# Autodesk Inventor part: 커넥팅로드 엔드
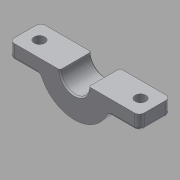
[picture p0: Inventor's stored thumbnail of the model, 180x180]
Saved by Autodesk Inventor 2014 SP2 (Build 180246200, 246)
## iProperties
Created: 2016-11
Part Number: 커넥팅로드 엔드
Material: 알루미늄 6061
Document SubType Name: Modeling
Designer: mduedu
Density: 2.71 g/cm^3
Mass: 15.0819 g
Surface Area: 26.6719 cm^2
Volume: 5.56529 cm^3
Appearance: 알루미늄 - 평지
Author: mduedu
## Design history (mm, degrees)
sketch "스케치1" dims "d0" = 30, "d3" = 15
  geometry: L1 (0, 0)-(0, 96); L2 (-5, 90.41)-(-10, 11.18); L3 (5, 90.41)-(10, 11.18); C1 r 6 at (0, 0); C2 r 4 at (0, 96); 3 further points
  constraints: 6 end point, 4 coincident, 2 centre point, 2 symmetric about line, 1 vertical, 6 other
  dimensions: "d1" = 12 diameter of C1; "d2" = 8 diameter of C2; "d4" = 96 distance of L1.start L1.end; "d6" = 10 distance from line of L1 L2.end; "d7" = 5 distance from line of L1 L2.start
extrude "돌출1" new body sketch "스케치1" stored distance "d8" = 13; taper "d9" = 0 deg
extrude "돌출2" join sketch "스케치1" stored distance "d10" = 32; taper "d11" = 0 deg
sketch "스케치2"
  geometry: L1 (5, 90.41)-(10, 11.18) reference; L2 (-5, 90.41)-(-10, 11.18) reference; A1 r 7.5 centre (0, 96) between (5, 90.41) and (-5, 90.41) reference; A2 r 15 centre (0, 0) between (10, 11.18) and (-10, 11.18) reference
extrude "돌출3" join sketch "스케치2" stored distance "d12" = 8; taper "d13" = 0 deg
sketch "스케치3"
  geometry: L1 (-2.732, 78.715)-(-6.171, 24.226); L2 (2.732, 78.715)-(6.171, 24.226); L3 (0, 78.5)-(0, 25); A1 r 17.5 centre (0, 96) between (-2.732, 78.715) and (2.732, 78.715); A2 r 25 centre (0, 0) between (6.171, 24.226) and (-6.171, 24.226); 9 further points; 2 other entities
  constraints: 6 end point, 6 point on circle, 2 centre point, 1 symmetric about line, 1 vertical alignment, 6 other
  dimensions: "d18" = 10 dimension on A1; "d19" = 10 dimension on A2; "d20" = 3 dimension on L1
extrude "돌출4" cut sketch "스케치3" distance "d21" = 2; taper "d22" = 0 deg
fillet "모깎기1" dims "d23" = 2
fillet "모깎기2" dims "d24" = 2
fillet "모깎기3" dims "d25" = 1
chamfer "모따기1" distance "d26" = 0.5; stored, may be unused: second distance "d27" = 2, angle "d28" = 45 deg
sketch "스케치4"
  geometry: L1 (-27, -6)-(-13.748, -6); L2 (27, -6)-(27, 6); L3 (27, 6)-(13.748, 6); L4 (-27, 6)-(-27, -6); L5 (-27, -6)-(27, 6); L6 (27, -6)-(-27, 6); L7 (-13.748, 6)-(-27, 6); L8 (13.748, 6)-(-13.748, 6); L9 (13.748, -6)-(27, -6); L10 (-13.748, -6)-(13.748, -6); A1 r 15 centre (0, 0) between (-13.748, 6) and (13.748, 6) reference; 1 further point
  constraints: 20 end point, 10 parallel, 4 point on circle, 3 horizontal, 3 perpendicular, 2 midpoint
  dimensions: "d29" = 54 distance of L1.start L2.start; "d31" = 12 distance of L2.start L2.end
extrude "돌출5" join sketch "스케치4" stored distance "d32" = 0; taper "d33" = 0 deg
fillet "모깎기4" dims "d34" = 2
fillet "모깎기5" dims "d35" = 1
fillet "모깎기6" dims "d36" = 1
sketch "스케치5"
  geometry: L1 (1, 0)-(1, 9) reference; L2 (-18.5, 20.5)-(-33.5, 20.5) reference; L3 (-33.5, -11.5)-(-18.5, -11.5) reference; L4 (-26, 20.5)-(-26, -11.5); 3 further points
  constraints: 2 end point, 2 midpoint, 1 horizontal alignment, 1 symmetric about line
  dimensions: "d37" = 6 distance from line of point (-5, 4.5) L1
feature "분할1"
sketch "스케치7"
  geometry: 2 further points
  constraints: 2 other
hole "구멍2" sketch "스케치7" at (-47, 4.5), (-5, 4.5) diameter "d45" = 4.5; stored, may be unused: countersink angle "d49" = 90 deg, drill point angle "d51" = 0 deg; dims "d46" = 6, "d47" = 4, "d48" = 2, "d50" = 8
node "솔리드1"
mirror "대칭1"
other parameters: "d16" = 4, "d17" = 4
